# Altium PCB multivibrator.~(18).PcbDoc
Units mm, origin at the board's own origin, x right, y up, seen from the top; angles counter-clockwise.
Board outline 30 x 30 mm, 2 copper layers (Top Layer, Bottom Layer), stack 1.569 mm thick; 9 components, 6 nets, 20 pads, 1 vias.
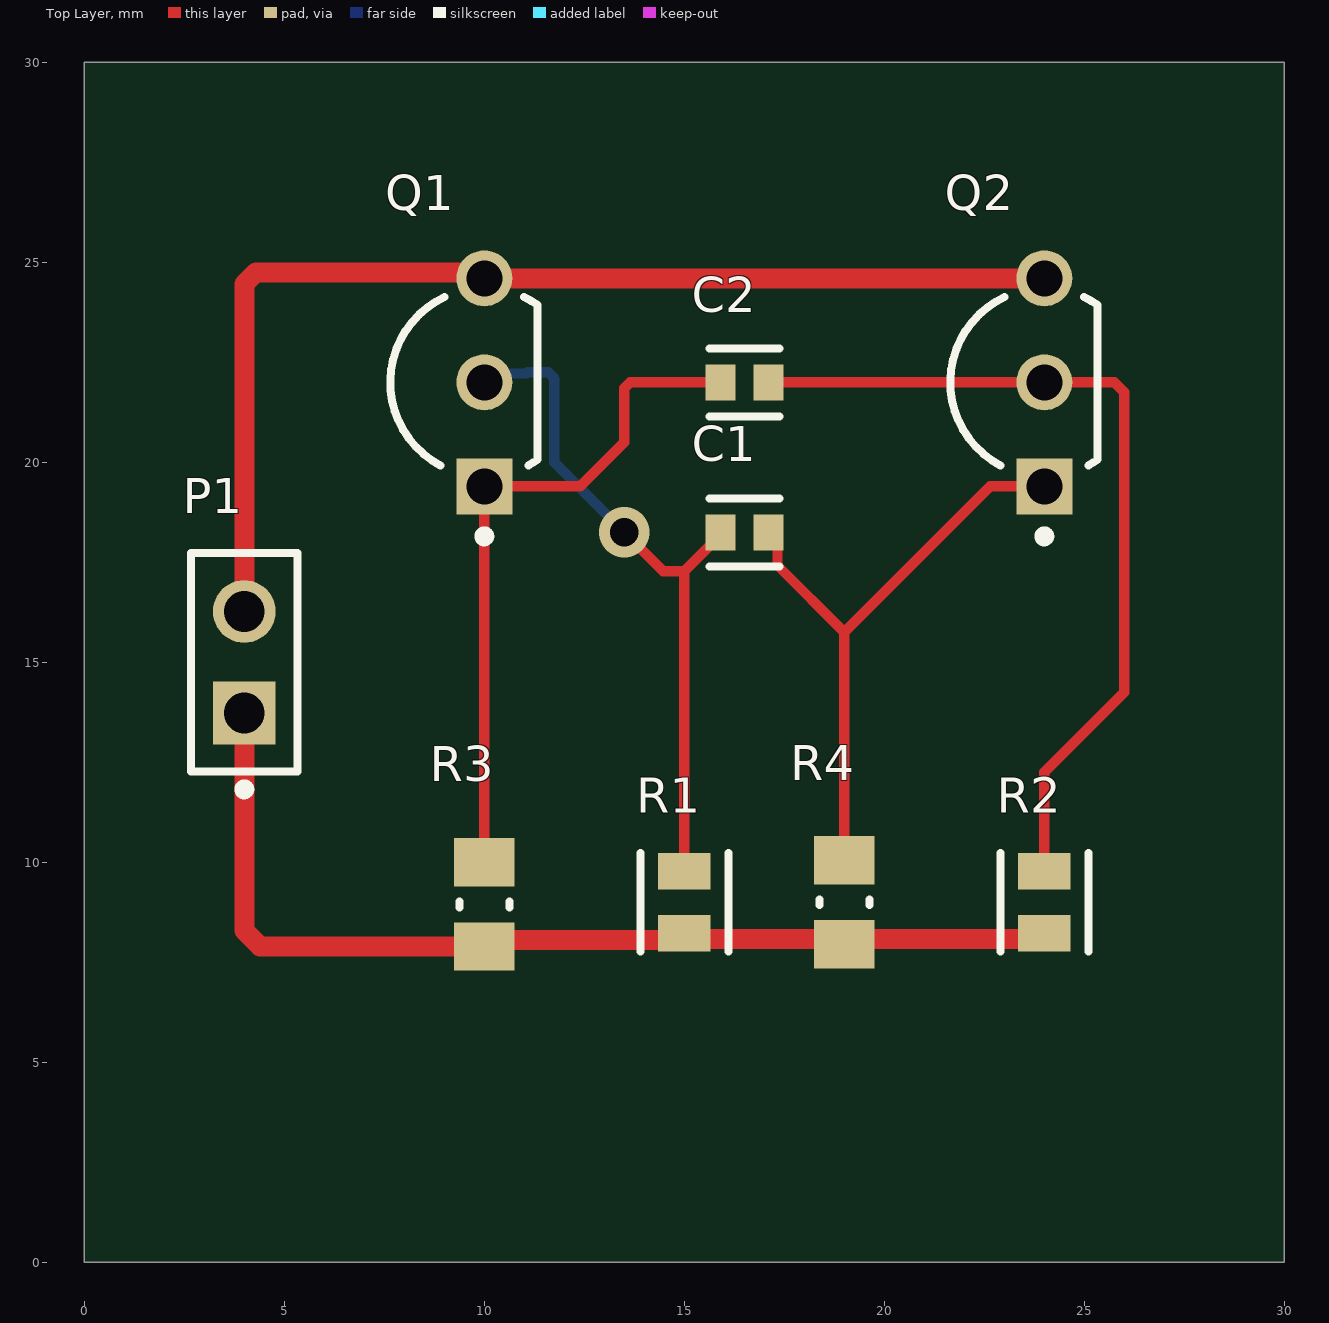
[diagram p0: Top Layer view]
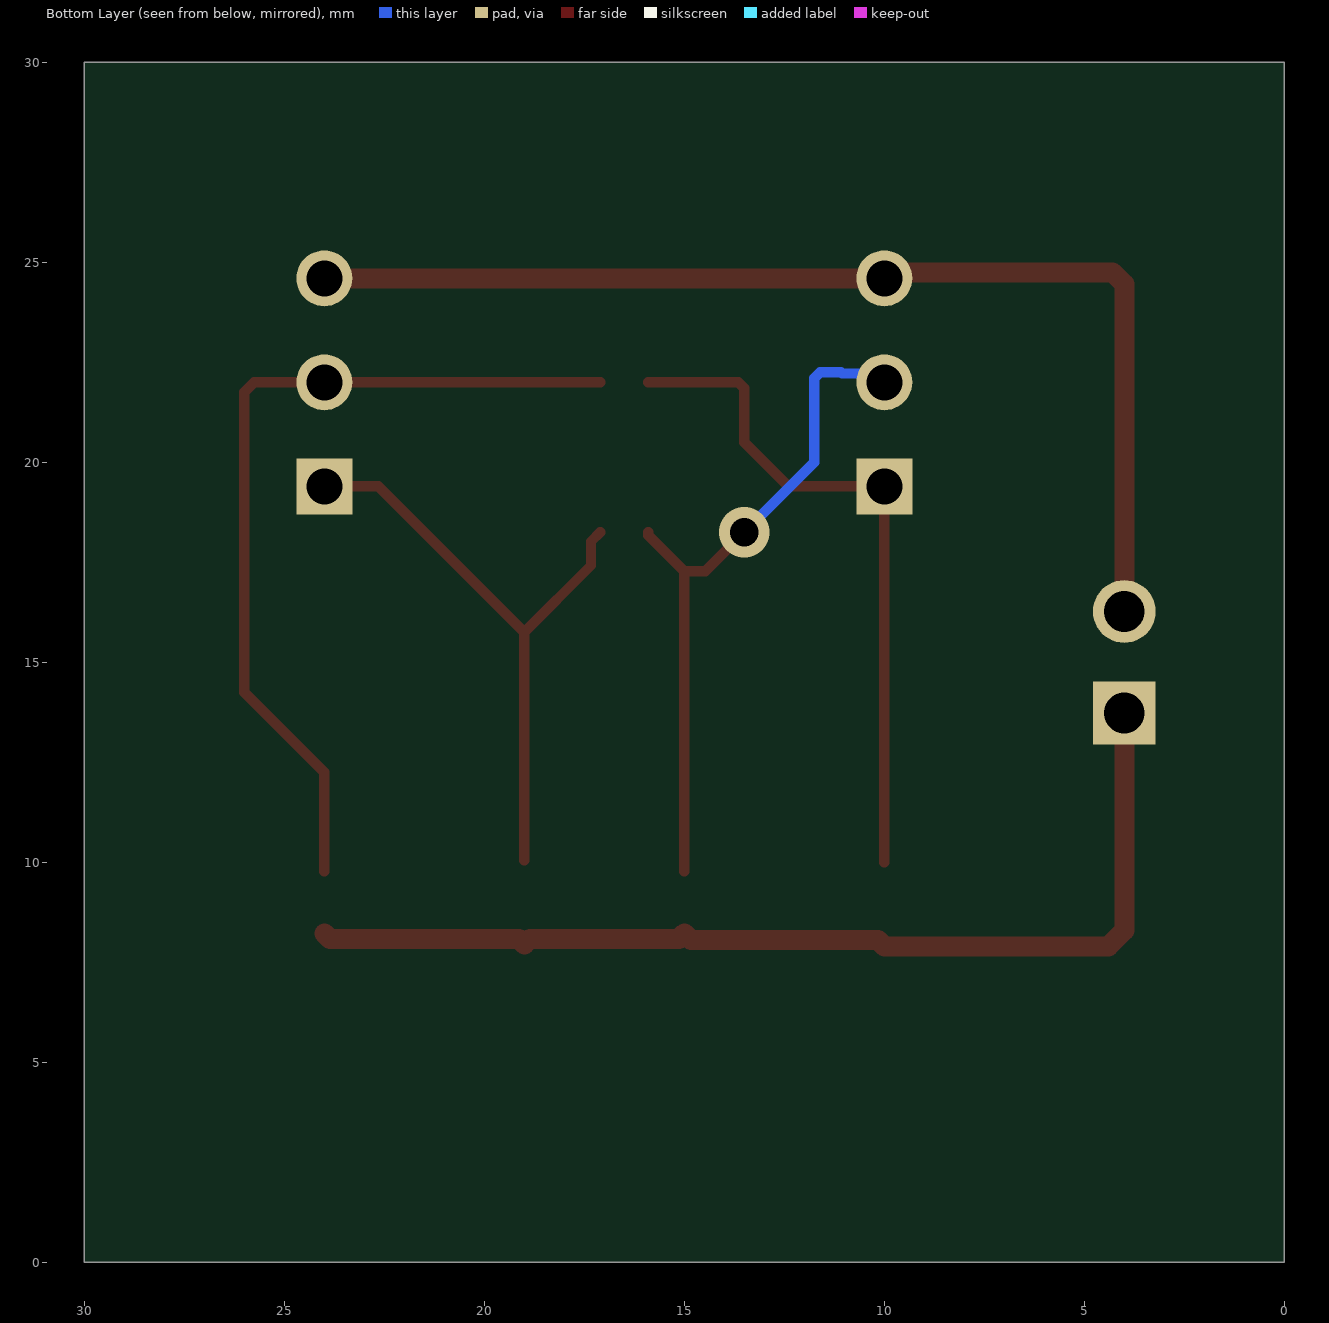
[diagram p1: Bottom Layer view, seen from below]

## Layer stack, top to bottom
Top Solder: solder mask 0.0254, SM-001, Dk 4
Top Layer: signal copper 0.035
Dielectric 1: core 1.4986, Core-043, Dk 4.3
Bottom Layer: signal copper 0.035
Bottom Solder: solder mask 0.0254, SM-001, Dk 4

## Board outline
0,0 30,0 30,30 0,30

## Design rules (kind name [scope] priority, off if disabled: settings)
Clearance [All] p1: gap=0.254 ignorepadtopadclearanceinfootprint=FALSE
PolygonConnect [All] p1: connectstyle=Relief reliefconductorwidth=0.254 reliefentries=4 polygonreliefangle="90 Angle" airgapwidth=0.254
RoutingVias [All] p1: holewidth=0.711 width=1.27 viastyle="Through Hole" minholewidth=0.711 minwidth=1.27 maxholewidth=0.711 maxwidth=1.27
SolderMaskExpansion [All] p1: expansion=0.102 istentingtop=FALSE
Width Width_2 [InNet('GND')] p1: maxlimit=0.5 minlimit=0.254 preferedwidth=0.5 minimp=50.000000 maximp=50.000000 favimp=50.000000
Width Width_1 [InNet('12V')] p2: maxlimit=0.5 minlimit=0.254 preferedwidth=0.5 minimp=50.000000 maximp=50.000000 favimp=50.000000
Width [All] p3: maxlimit=0.254 minlimit=0.2 preferedwidth=0.254 minimp=50.000000 maximp=50.000000 favimp=50.000000
30 further rules are at their usual default settings.

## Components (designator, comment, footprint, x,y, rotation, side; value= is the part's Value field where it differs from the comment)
C1 "C0603C223J4RACTU" FP-C0603C-CF-MFG 16.5,18.25 r0 top value="22,000 pF"
C2 "C0603C223J4RACTU" FP-C0603C-CF-MFG 16.5,22 r0 top value="22,000 pF"
P1 "TSW-102-07-F-S" FP-TSW-102-07-F-S-MFG 4,15 r90 top
Q1 "BC547CZL1G" ONSC-TO-92-3-29-11_AM_BL 10,22 r90 top
Q2 "BC547CZL1G" ONSC-TO-92-3-29-11_AM_BL 24,22 r90 top
R1 "CRGCQ0805J100K" FP-CRGCQ0805-IPC_C 15,9 r90 top value=100KΩ
R2 "CRGCQ0805J100K" FP-CRGCQ0805-IPC_C 24,9 r90 top value=100KΩ
R3 "CRCW08051K00JNEC" FP-CRCW0805-e3-IPC_A 10,8.949 r90 top
R4 "CRCW08051K00JNEC" FP-CRCW0805-e3-IPC_A 19,9 r90 top

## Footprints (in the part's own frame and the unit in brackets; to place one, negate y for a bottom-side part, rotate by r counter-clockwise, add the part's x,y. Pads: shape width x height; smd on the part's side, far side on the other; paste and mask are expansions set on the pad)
FP-C0603C-CF-MFG [mm]
  rect 0.75x0.9 smd paste+0 mask+0: 1(-0.6,0) 2(0.6,0)
  silkscreen extent -0.87,-0.85 0.88,0.85, body extent -1.2,-0.6 1.2,0.6, height 0.25
FP-CRCW0805-e3-IPC_A [mil]
  rect 47.5x59.38 smd paste+0 mask+0: 1(-41.37,0) 2(41.37,0)
  silkscreen extent -3,-25 3,25, body extent -85,-49 85,49, height 10
FP-CRGCQ0805-IPC_C [mm]
  rect 0.906x1.31 smd paste+0 mask+0: 1(-0.776,0) 2(0.776,0)
  silkscreen extent -1.23,-1.1 1.23,1.1, body extent -1.33,-0.8 1.33,0.8, height 0.25
FP-TSW-102-07-F-S-MFG [mm]
  rect 1.57x1.57 hole 1.02 paste-2539.97 mask+0: 1(-1.27,0)
  round 1.57 hole 1.02 paste-2539.97 mask+0: 2(1.27,0)
  silkscreen extent -3.3,-1.34 2.73,1.34, body extent -2.83,-1.44 2.83,1.44, height 0.25
ONSC-TO-92-3-29-11_AM_BL [mm] "TO, 3-Leads, Body Dia 4.7mm, Pitch 2.6mm"
  rect 1.4x1.4 hole 0.9: 1(-2.6,0)
  round 1.4 hole 0.9: 2(0,0) 3(2.6,0)
  silkscreen extent -3.97,-1.34 2.13,2.35, body extent -2.84,-1.34 2.84,2.35, height 5.33

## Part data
C1 C2: library part CMP-2006-03745-2, "CAP CER 0.022UF 16V 5% X7R 0603", Capacitance="22,000 pF", Manufacturer=KEMET, Package=C0603C-CF, Temperature="-55°C to +125°C", Temperature Characteristic=X7R, Temperature Coefficient=30ppm/°C, Temperature Range High=+125°C, Temperature Range Low=-55°C, Tolerance=0.05, Voltage Rating="16 V"
P1: library part CMP-02766-001458-1, "CONN HEADER VERT 2POS 2.54MM", Color=Black, Flammability Rating="UL94 V-0", Max Current Rating=7.6A, Max Operating Temperature=125°C, Max Voltage Rating (AC)=550V, Min Operating Temperature=-55°C, Package Quantity=1
Q1 Q2: library part CMP-1048-01606-1, "Amplifier Transistor, NPN Silicon, 3-Pin TO-92, Pb-Free, Ammo Box", Manufacturer="On Semiconductor"
R1 R2: library part CMP-03211-009742-1, "CRGCQ0805 100KΩ 0.125W ±100ppm/°C 5% 150V", Ambient Temperature Range High=+70°C, Manufacturer="TE Connectivity", Package=CRGCQ0805, Power Rating=0.125W, Resistance=100KΩ, Temperature="-55°C to +155°C", Temperature Coefficient=±100ppm/°C, Temperature Range High=+155°C, Temperature Range Low=-55°C, Tolerance=0.05, Voltage Rating=150V
R3 R4: library part CMP-02407-005778-1, "RES Thick Film, 1kΩ, 5%, 0.125W, 200ppm/°C, 0805", Case/Package=0805, Max Operating Temperature=155°C, Max Power Dissipation=125mW, Min Operating Temperature=-55°C, Package Quantity=20000, Resistance=1kR, Temperature Coefficient=200ppm/°C, Tolerance=5%

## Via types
v1: diameter 1.27, hole 0.711, Top Layer to Bottom Layer, 1 vias

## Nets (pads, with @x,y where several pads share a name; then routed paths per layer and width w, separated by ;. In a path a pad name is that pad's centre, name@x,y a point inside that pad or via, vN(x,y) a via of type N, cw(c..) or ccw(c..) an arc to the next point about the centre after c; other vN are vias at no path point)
12V: P1.1 R1.1 R2.1 R3.1 R4.1 | length 26
  Top Layer w0.5: P1.1 4,8.293 4.395,7.898 R3.1 10.163,8.061 14.837,8.061 R1.1 15.137,8.087 18.863,8.087 R4.1 19.137,8.087 23.863,8.087 R2.1
GND: P1.2 Q1.3 Q2.3 | length 28.4
  Top Layer w0.5: P1.2 4,24.457 4.293,24.75 9.85,24.75 Q1.3 Q2.3
NetC1_1: C1.1 Q1.2 R1.2 | length 17.2
  Top Layer w0.254: v1(13.5,18.25) 14.475,17.275 15,17.275 ; R1.2 15,17.275 ; C1.1 15.9,18.175 15,17.275
  Bottom Layer w0.254: Q1.2 10.219,22.219 11.05,22.219 11.081,22.25 11.601,22.25 11.75,22.101 11.75,20 v1(13.5,18.25)
NetC1_2: C1.2 Q2.1 R4.2 | length 15.5
  Top Layer w0.254: C1.2 17.331,18.019 17.331,17.419 19,15.75 ; R4.2 19,15.75 ; Q2.1 22.65,19.4 19,15.75
NetC2_1: C2.1 Q1.1 R3.2 | length 17.2
  Top Layer w0.254: R3.2 Q1.1 12.4,19.4 13.5,20.5 13.5,21.851 13.649,22 C2.1
NetC2_2: C2.2 Q2.2 R2.2 | length 21.8
  Top Layer w0.254: C2.2 Q2.2 25.75,22 26,21.75 26,14.25 24,12.25 R2.2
